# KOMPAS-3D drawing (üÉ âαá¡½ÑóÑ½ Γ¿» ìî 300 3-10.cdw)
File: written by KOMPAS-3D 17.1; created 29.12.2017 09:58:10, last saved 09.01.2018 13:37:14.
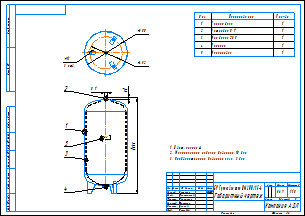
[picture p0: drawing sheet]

Sheet 1: A3, landscape, title-block layout from C:\Лощинин\GRAPHIC.LYT style 1

Title block, sheet 1: name: БР Гранлевел тип НМ 300/1,5-6 / Габаритный чертеж; mass: 56,9; sheets: 1; sheet format: A3; stored path: \\Fsk1\files\АП\20_PKO\02_Насосное направление\Разработка\04_Проекты разные\Баки\КД действующая\Баки Flexcon R\Компас\Чертежи\БР Гранлевел тип НМ 300 1,5-6.cdw; drawn by: Лощинин; checked by: Хантимеров; drawn by, date: 29.12.2017

Views: Проекционный вид 2
Referenced files in \\Fsk1\files\АП\20_PKO\02_Насосное направление\Разработка\04_Проекты разные\Баки\КД действующая\Баки Flexcon R\Компас\: 300 литров.a3d, 16302_Flexcon_300_1-6.m3d
Referenced files in C:\Лощинин\: GRAPHIC.LYT
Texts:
  IvAn
  ADL
  Поз.
  Кол-во
  Корпус бака
  Мембрана SBR
  Патрубок G 1"
  Ниппель
  Маркировка
  АДЛ
  Цвет: красный
  Максимальное рабочее давление: 10 бар
  Предварительное давление газа: 3 бар
  ACAD_ISO03W100_RGB_223_127_255_SC_0.063_THICK_0.05
  ACAD_ISO03W100_RGB_223_127_255_SC_1_THICK_0.05
  Лит-Масса-Масштаб
  Материал-Предприятие
  Масштаб
  Изм.
  Лист
  № докум.
  Подп.
  Дата
  Лит.
  Разраб.
  Пров.
  Т.контр.
  Курлыкина
  Листов
  Нач.отд.
  Щетинин
  Н.контр.
  Долгов
  Утв.
  Рашидов
  Компания АДЛ
  Изменение
  Номер документа
  Подпись
  Обозначение документа
  Наименование изделия
  Масса изделия по ГОСТ 2.109-73
  Порядковый номер листа
  Общее количество листов в документе
  Характер работы, выполненной лицом, подписавшим документ
  Наименование или индекс предприятия, выпускающего документ
  Инв. № подл.
  Подп. и дата
  Взам. инв. №
  Инв. № дубл.
  Инвентарный номер подлинника по ГОСТ 2.501-68
  Подпись принявшего подлинник в отдел технической документации
  Инвентарный номер подлинника, взамен которого выпущен данный подлинник
  Инвентарный номер дубликата по ГОСТ 2.502-68
  Подпись принявшего дубликат в отдел технической документации
  Справ. №
  Перв. примен.
  Обозначение документа, взамен или на основании которого выпущен данный документ
  Обозначение документа, в котором впервые записан данный документ
  Подпись лица, копировавшего чертеж
  Обозначение формата листа
Dimensions and other numbers on the sheet: 1; 3; 2; 4; 5; 1330; 21; 1:10; 56,9; 29.12.2017; 16302_Flexcon_300_1-6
